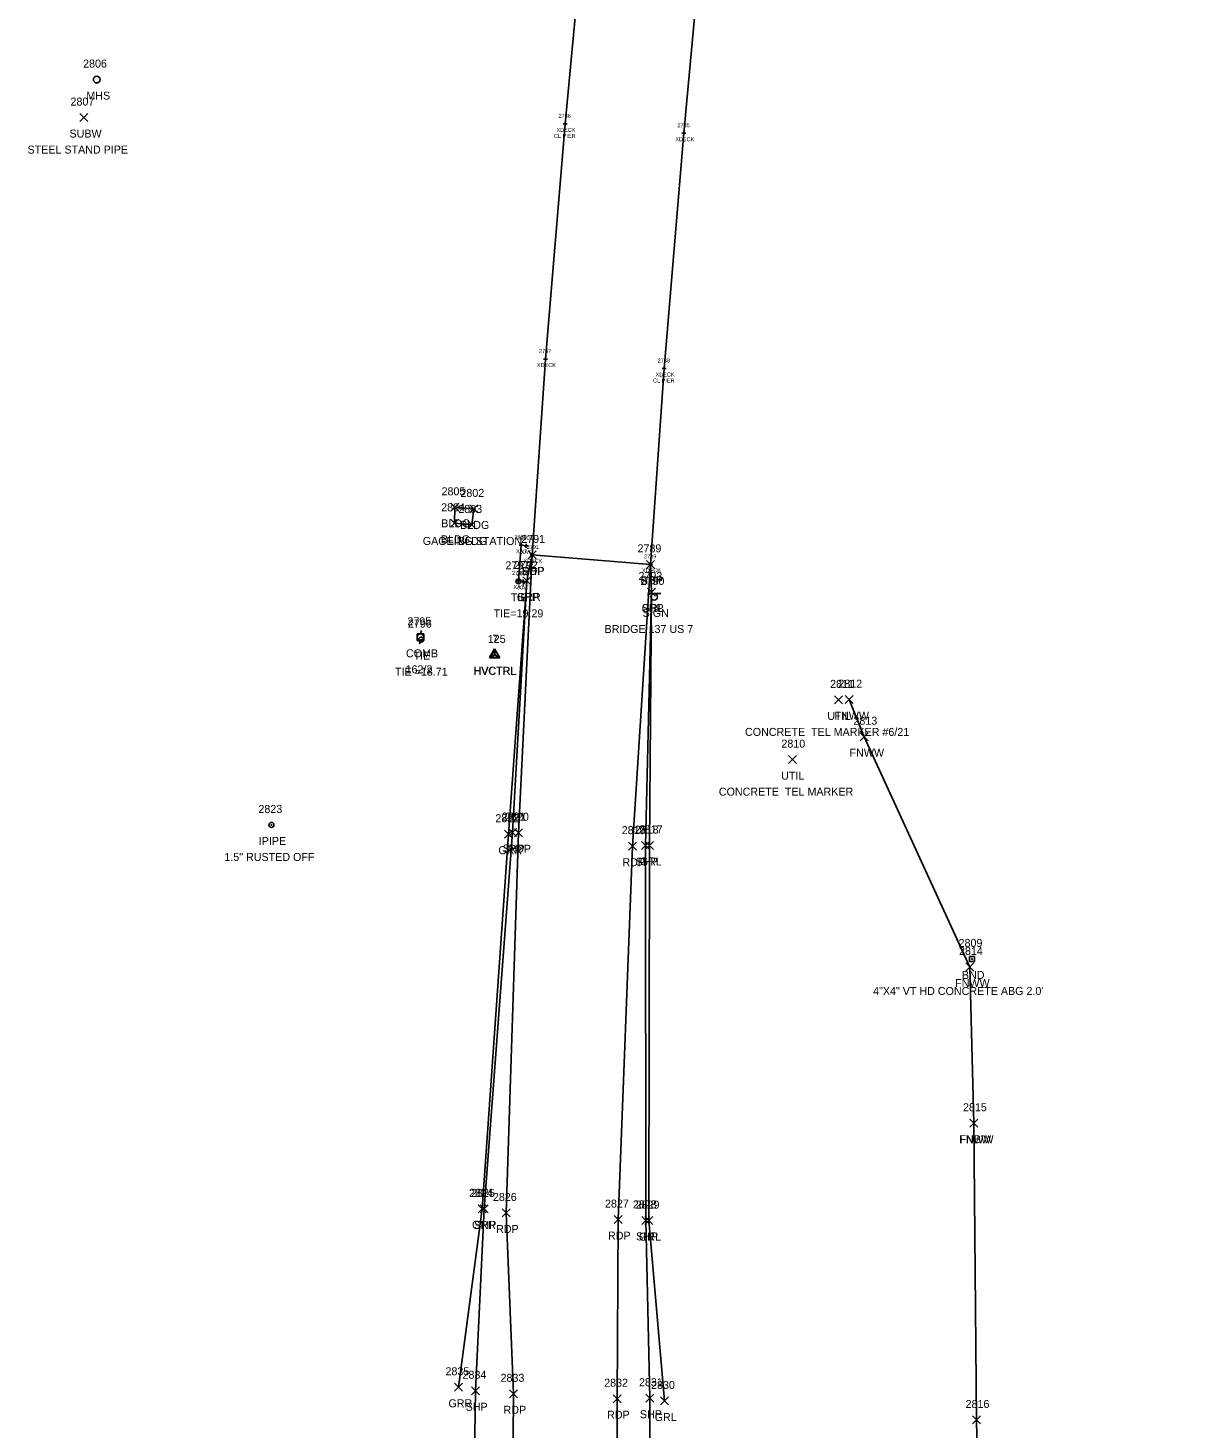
# Model space of a CAD drawing. Extents: x 1443071 to 1445292, y 614024 to 622563.
# Drawn here: x 1443904.7 to 1444198.2, y 619541.5 to 619891.2 of the extents above; entities that cross this region are included whole.
import ezdxf

# ---------------------------------------------------------------- set-up
doc = ezdxf.new("R2010")
doc.units = 0
for name, color, linetype in [('B_A', 7, 'Continuous'), ('B_C', 7, 'Continuous'), ('B_I', 7, 'Continuous'), ('B_TIC', 7, 'Continuous'), ('BELB', 7, 'Continuous'), ('BSUBM', 7, 'Continuous'), ('C_A', 7, 'Continuous'), ('C_C', 7, 'Continuous'), ('C_I', 7, 'Continuous'), ('CBP', 7, 'Continuous'), ('CPSM', 7, 'Continuous'), ('L_A', 7, 'Continuous'), ('L_C', 7, 'Continuous'), ('L_I', 7, 'Continuous'), ('L_TIC', 7, 'Continuous'), ('LBC', 7, 'Continuous'), ('LFNC', 7, 'Continuous'), ('M_A', 7, 'Continuous'), ('M_C', 7, 'Continuous'), ('M_I', 7, 'Continuous'), ('MHBP', 7, 'Continuous'), ('MPIP', 7, 'Continuous'), ('P_A', 7, 'Continuous'), ('P_I', 7, 'Continuous'), ('P_TIC', 7, 'Continuous'), ('PET', 7, 'Continuous'), ('PSP', 7, 'Continuous'), ('R_A', 7, 'Continuous'), ('R_I', 7, 'Continuous'), ('R_TIC', 7, 'Continuous'), ('RGR', 7, 'Continuous'), ('S_A', 7, 'Continuous'), ('S_C', 7, 'Continuous'), ('S_I', 7, 'Continuous'), ('SSGN', 7, 'Continuous'), ('U_A', 7, 'Continuous'), ('U_C', 7, 'Continuous'), ('U_I', 7, 'Continuous'), ('U_TIC', 7, 'Continuous'), ('UDEFAULT', 7, 'Continuous'), ('UP', 7, 'Continuous'), ('USMH', 7, 'Continuous')]:
    doc.layers.add(name, color=color, linetype=linetype)

msp = doc.modelspace()

# ---------------------------------------------------------------- linework, layer by layer
at = {"layer": 'B_TIC'}
for p, q in [((1444038.87, 619867.29), (1444038.95, 619867.29)), ((1444068.55, 619864.95), (1444068.62, 619864.95)), ((1444033.97, 619808.54), (1444034.05, 619808.54)), ((1444063.62, 619806.17), (1444063.69, 619806.17)), ((1444027.91, 619762.01), (1444027.98, 619762.01)), ((1444029.1, 619761.87), (1444029.18, 619761.87)), ((1444030.6, 619759.6), (1444030.67, 619759.6)), ((1444060.23, 619757.24), (1444060.31, 619757.24)), ((1444027.24, 619753.1), (1444027.32, 619753.1)), ((1444028.38, 619752.95), (1444028.45, 619752.95))]:
    msp.add_line(p, q, dxfattribs=at)
for points in [[(1444038.37, 619867.29), (1444039.37, 619867.29)], [(1444038.87, 619866.79), (1444038.87, 619867.79)], [(1444068.05, 619864.95), (1444069.05, 619864.95)], [(1444068.55, 619864.45), (1444068.55, 619865.45)], [(1444033.47, 619808.54), (1444034.47, 619808.54)], [(1444033.97, 619808.04), (1444033.97, 619809.04)], [(1444063.11, 619806.17), (1444064.11, 619806.17)], [(1444063.61, 619805.67), (1444063.61, 619806.67)], [(1444027.4, 619762.01), (1444028.4, 619762.01)], [(1444027.9, 619761.51), (1444027.9, 619762.51)], [(1444028.6, 619761.87), (1444029.6, 619761.87)], [(1444029.1, 619761.37), (1444029.1, 619762.37)], [(1444030.1, 619759.6), (1444031.1, 619759.6)], [(1444030.6, 619759.1), (1444030.6, 619760.1)], [(1444059.73, 619757.24), (1444060.73, 619757.24)], [(1444060.23, 619756.74), (1444060.23, 619757.74)], [(1444026.74, 619753.1), (1444027.74, 619753.1)], [(1444027.24, 619752.6), (1444027.24, 619753.6)], [(1444027.88, 619752.95), (1444028.88, 619752.95)], [(1444028.38, 619752.45), (1444028.38, 619753.45)]]:
    msp.add_lwpolyline(points, dxfattribs=at)
at = {"layer": 'BELB'}
for points in [[(1444043.42, 619916.17), (1444038.87, 619867.29), (1444033.97, 619808.54), (1444030.6, 619759.6)], [(1444073.05, 619913.75), (1444068.55, 619864.95), (1444063.61, 619806.17), (1444060.23, 619757.24)]]:
    msp.add_lwpolyline(points, dxfattribs=at)
at = {"layer": 'BSUBM'}
msp.add_lwpolyline([(1444028.38, 619752.95), (1444027.24, 619753.1), (1444027.9, 619762.01), (1444029.1, 619761.87)], dxfattribs=at)
at = {"layer": 'CBP'}
for centre, radius in [((1444027.22, 619753), 0.625), ((1444027.22, 619753), 0.0833), ((1444002.92, 619738.44), 0.625), ((1444002.92, 619738.44), 0.0833)]:
    msp.add_circle(centre, radius, dxfattribs=at)
at = {"layer": 'CPSM'}
for p, q in [((1444019.99, 619733.94), (1444021.24, 619736.1)), ((1444019.99, 619733.94), (1444021.24, 619734.66)), ((1444019.99, 619733.94), (1444022.49, 619733.94)), ((1444020.1, 619733.9), (1444021.35, 619736.07)), ((1444020.1, 619733.9), (1444021.35, 619734.62)), ((1444020.1, 619733.9), (1444022.6, 619733.9)), ((1444022.49, 619733.94), (1444021.24, 619736.1)), ((1444021.24, 619734.66), (1444021.24, 619736.1)), ((1444021.24, 619734.66), (1444021.24, 619734.66)), ((1444021.24, 619734.66), (1444022.49, 619733.94)), ((1444022.6, 619733.9), (1444021.35, 619736.07)), ((1444021.35, 619734.62), (1444021.35, 619736.07)), ((1444021.35, 619734.62), (1444021.35, 619734.62)), ((1444021.35, 619734.62), (1444022.6, 619733.9))]:
    msp.add_line(p, q, dxfattribs=at)
at = {"layer": 'L_TIC'}
for points in [[(1444010.34, 619770.49), (1444012.34, 619772.49)], [(1444012.34, 619770.49), (1444010.34, 619772.49)], [(1444010.34, 619770.49), (1444012.34, 619772.49)], [(1444012.34, 619770.49), (1444010.34, 619772.49)], [(1444015.05, 619770.09), (1444017.05, 619772.09)], [(1444017.05, 619770.09), (1444015.05, 619772.09)], [(1444015.05, 619770.09), (1444017.05, 619772.09)], [(1444017.05, 619770.09), (1444015.05, 619772.09)], [(1444010.23, 619766.5), (1444012.23, 619768.5)], [(1444012.23, 619766.5), (1444010.23, 619768.5)], [(1444014.53, 619766.09), (1444016.53, 619768.09)], [(1444016.53, 619766.09), (1444014.53, 619768.09)], [(1444108.81, 619722.44), (1444110.81, 619724.44)], [(1444110.81, 619722.44), (1444108.81, 619724.44)], [(1444112.59, 619713.18), (1444114.59, 619715.18)], [(1444114.59, 619713.18), (1444112.59, 619715.18)], [(1444138.95, 619655.65), (1444140.95, 619657.65)], [(1444140.95, 619655.65), (1444138.95, 619657.65)], [(1444139.95, 619616.62), (1444141.95, 619618.62)], [(1444141.95, 619616.62), (1444139.95, 619618.62)], [(1444139.95, 619616.62), (1444141.95, 619618.62)], [(1444141.95, 619616.62), (1444139.95, 619618.62)], [(1444140.66, 619542.48), (1444142.66, 619544.48)], [(1444142.66, 619542.48), (1444140.66, 619544.48)]]:
    msp.add_lwpolyline(points, dxfattribs=at)
at = {"layer": 'LBC'}
for points in [[(1444016.05, 619771.09), (1444015.53, 619767.09), (1444011.23, 619767.5), (1444011.34, 619771.49)], [(1444016.05, 619771.09), (1444011.34, 619771.49)]]:
    msp.add_lwpolyline(points, dxfattribs=at)
at = {"layer": 'LFNC'}
for points in [[(1444109.81, 619723.44), (1444113.59, 619714.18), (1444139.95, 619656.65), (1444140.95, 619617.62)], [(1444140.95, 619617.62), (1444141.66, 619543.48), (1444143.47, 619453.28), (1444144.69, 619378.28), (1444145.89, 619275.11), (1444147.59, 619182.81), (1444151.11, 619052.76), (1444160.95, 618964.58), (1444173.83, 618850.02), (1444185.25, 618752.69), (1444198.22, 618656.01)]]:
    msp.add_lwpolyline(points, dxfattribs=at)
at = {"layer": 'MHBP'}
msp.add_lwpolyline([(1444139.88, 619659.28), (1444141.13, 619659.28), (1444141.13, 619658.03), (1444139.88, 619658.03)], close=True, dxfattribs=at)
msp.add_circle((1444140.5, 619658.66), 0.0833, dxfattribs=at)
at = {"layer": 'MPIP'}
for radius in [0.625, 0.0833]:
    msp.add_circle((1443965.51, 619692.14), radius, dxfattribs=at)
at = {"layer": 'P_TIC'}
for points in [[(1444029.6, 619758.6), (1444031.6, 619760.6)], [(1444031.6, 619758.6), (1444029.6, 619760.6)], [(1444029.6, 619758.6), (1444031.6, 619760.6)], [(1444031.6, 619758.6), (1444029.6, 619760.6)], [(1444059.23, 619756.24), (1444061.23, 619758.24)], [(1444061.23, 619756.24), (1444059.23, 619758.24)], [(1444059.23, 619756.24), (1444061.23, 619758.24)], [(1444061.23, 619756.24), (1444059.23, 619758.24)], [(1444059.23, 619756.24), (1444061.23, 619758.24)], [(1444061.23, 619756.24), (1444059.23, 619758.24)], [(1444028.33, 619752.09), (1444030.33, 619754.09)], [(1444030.33, 619752.09), (1444028.33, 619754.09)], [(1444059.46, 619749.33), (1444061.46, 619751.33)], [(1444061.46, 619749.33), (1444059.46, 619751.33)], [(1444024.71, 619689.24), (1444026.71, 619691.24)], [(1444026.71, 619689.24), (1444024.71, 619691.24)], [(1444026.22, 619689.19), (1444028.22, 619691.19)], [(1444028.22, 619689.19), (1444026.22, 619691.19)], [(1444057.96, 619685.98), (1444059.96, 619687.98)], [(1444059.96, 619685.98), (1444057.96, 619687.98)], [(1444054.7, 619685.84), (1444056.7, 619687.84)], [(1444056.7, 619685.84), (1444054.7, 619687.84)], [(1444017.62, 619595.21), (1444019.62, 619597.21)], [(1444019.62, 619595.21), (1444017.62, 619597.21)], [(1444023.14, 619594.2), (1444025.14, 619596.2)], [(1444025.14, 619594.2), (1444023.14, 619596.2)], [(1444051.09, 619592.54), (1444053.09, 619594.54)], [(1444053.09, 619592.54), (1444051.09, 619594.54)], [(1444058.06, 619592.34), (1444060.06, 619594.34)], [(1444060.06, 619592.34), (1444058.06, 619594.34)], [(1444015.49, 619549.78), (1444017.49, 619551.78)], [(1444017.49, 619549.78), (1444015.49, 619551.78)], [(1444025, 619549.02), (1444027, 619551.02)], [(1444027, 619549.02), (1444025, 619551.02)], [(1444050.88, 619547.79), (1444052.88, 619549.79)], [(1444052.88, 619547.79), (1444050.88, 619549.79)], [(1444059.01, 619547.92), (1444061.01, 619549.92)], [(1444061.01, 619547.92), (1444059.01, 619549.92)]]:
    msp.add_lwpolyline(points, dxfattribs=at)
at = {"layer": 'PET'}
for points in [[(1444060.23, 619757.24), (1444030.6, 619759.6), (1444027.22, 619690.19), (1444024.14, 619595.2), (1444026, 619550.02), (1444025.36, 619470.06), (1444027.67, 619387.44), (1444035.05, 619262.29), (1444046.36, 619146.08), (1444057.76, 619040.09), (1444068.86, 618946.58), (1444081.65, 618839.75), (1444094.51, 618740.27), (1444109.49, 618620.85), (1444119.47, 618545.62)], [(1444060.23, 619757.24), (1444055.7, 619686.84), (1444052.09, 619593.54), (1444051.88, 619548.79), (1444051.53, 619469.84), (1444057.39, 619386.89), (1444060.43, 619264.84), (1444070.47, 619153.76), (1444082.27, 619042.98), (1444093.27, 618950.3), (1444106.23, 618841.72), (1444119.2, 618742.75), (1444134.15, 618623.05), (1444144.16, 618546.64)]]:
    msp.add_lwpolyline(points, dxfattribs=at)
at = {"layer": 'PSP'}
for points in [[(1444030.6, 619759.6), (1444029.33, 619753.09), (1444025.71, 619690.24), (1444018.62, 619596.21), (1444016.49, 619550.78), (1444015.83, 619506.94), (1444016.35, 619478.84), (1444019.52, 619385.97), (1444025.45, 619273.62), (1444031.18, 619208.3), (1444036.73, 619143.63), (1444046.33, 619051.58), (1444050.41, 619020.07), (1444060.07, 618945.31), (1444073.2, 618838.48), (1444085.76, 618739.52), (1444101.61, 618620.44), (1444111.35, 618544.8)], [(1444060.23, 619757.24), (1444060.46, 619750.33), (1444058.96, 619686.98), (1444059.06, 619593.34), (1444060.01, 619548.92), (1444060.2, 619469.56), (1444062.86, 619388.02), (1444070.04, 619265.9), (1444080.12, 619155.61), (1444092.23, 619044.26), (1444103.72, 618951.36), (1444117.15, 618842.88), (1444129.88, 618744.38), (1444144.78, 618624.26), (1444154.69, 618549.98)]]:
    msp.add_lwpolyline(points, dxfattribs=at)
at = {"layer": 'R_TIC'}
for points in [[(1444028.33, 619752.09), (1444030.33, 619754.09)], [(1444030.33, 619752.09), (1444028.33, 619754.09)], [(1444059.46, 619749.33), (1444061.46, 619751.33)], [(1444061.46, 619749.33), (1444059.46, 619751.33)], [(1444023.71, 619688.83), (1444025.71, 619690.83)], [(1444025.71, 619688.83), (1444023.71, 619690.83)], [(1444058.98, 619686.03), (1444060.98, 619688.03)], [(1444060.98, 619686.03), (1444058.98, 619688.03)], [(1444017.13, 619595.23), (1444019.13, 619597.23)], [(1444019.13, 619595.23), (1444017.13, 619597.23)], [(1444058.75, 619592.28), (1444060.75, 619594.28)], [(1444060.75, 619592.28), (1444058.75, 619594.28)], [(1444011.24, 619550.65), (1444013.24, 619552.65)], [(1444013.24, 619550.65), (1444011.24, 619552.65)], [(1444062.68, 619547.23), (1444064.68, 619549.23)], [(1444064.68, 619547.23), (1444062.68, 619549.23)]]:
    msp.add_lwpolyline(points, dxfattribs=at)
at = {"layer": 'RGR'}
for points in [[(1444029.33, 619753.09), (1444024.71, 619689.83), (1444018.13, 619596.23), (1444012.24, 619551.65)], [(1444060.46, 619750.33), (1444059.98, 619687.03), (1444059.75, 619593.28), (1444063.68, 619548.23)]]:
    msp.add_lwpolyline(points, dxfattribs=at)
at = {"layer": 'SSGN'}
for p, q in [((1444059.44, 619749.95), (1444062.78, 619749.95)), ((1444061.09, 619749.12), (1444061.09, 619749.12))]:
    msp.add_line(p, q, dxfattribs=at)
msp.add_circle((1444061.09, 619749.12), 0.833, dxfattribs=at)
at = {"layer": 'U_TIC'}
for points in [[(1443917.65, 619867.86), (1443919.65, 619869.86)], [(1443919.65, 619867.86), (1443917.65, 619869.86)]]:
    msp.add_lwpolyline(points, dxfattribs=at)
at = {"layer": 'UDEFAULT'}
for points in [[(1444106.2, 619722.38), (1444108.2, 619724.38)], [(1444108.2, 619722.38), (1444106.2, 619724.38)], [(1444094.68, 619707.45), (1444096.68, 619709.45)], [(1444096.68, 619707.45), (1444094.68, 619709.45)]]:
    msp.add_lwpolyline(points, dxfattribs=at)
at = {"layer": 'UP'}
for p, q in [((1444002.98, 619740.68), (1444002.73, 619739.85)), ((1444001.89, 619738.18), (1444001.89, 619739.85)), ((1444001.89, 619739.85), (1444003.56, 619739.85)), ((1444003.56, 619738.18), (1444001.89, 619738.18)), ((1444002.48, 619737.35), (1444002.73, 619738.18)), ((1444002.73, 619739.02), (1444002.73, 619739.02)), ((1444003.56, 619739.85), (1444003.56, 619738.18))]:
    msp.add_line(p, q, dxfattribs=at)
msp.add_circle((1444002.73, 619739.02), 0.833, dxfattribs=at)
at = {"layer": 'USMH'}
for p, q in [((1443921.85, 619878.35), (1443921.85, 619878.35)), ((1443922.69, 619878.35), (1443922.69, 619878.35))]:
    msp.add_line(p, q, dxfattribs=at)
msp.add_circle((1443921.85, 619878.35), 0.833, dxfattribs=at)

# ---------------------------------------------------------------- texts
at = {"layer": 'B_A'}
for s, p in [('XDECK', (1444036.71, 619865.29)), ('XDECK', (1444066.39, 619862.95)), ('XDECK', (1444031.81, 619806.54)), ('XDECK', (1444061.45, 619804.17)), ('XAT', (1444026.61, 619760.01)), ('XAT', (1444027.8, 619759.87)), ('XDECK', (1444028.44, 619757.6)), ('XDECK', (1444058.07, 619755.24)), ('XAT', (1444025.94, 619751.1)), ('XAT', (1444027.08, 619750.95))]:
    msp.add_text(s, height=1, dxfattribs=at).set_placement(p)
at = {"layer": 'B_C'}
for p in [(1444036.1, 619863.79), (1444060.84, 619802.67)]:
    msp.add_text('CL PIER', height=1, dxfattribs=at).set_placement(p)
at = {"layer": 'B_I'}
for s, p in [('2786', (1444037.21, 619868.79)), ('2785', (1444066.92, 619866.45)), ('2787', (1444032.34, 619810.04)), ('2788', (1444061.98, 619807.67)), ('2800', (1444026.19, 619763.51)), ('2801', (1444027.71, 619763.37)), ('2791', (1444029.25, 619761.1)), ('2789', (1444058.59, 619758.74)), ('2799', (1444025.6, 619754.6)), ('2798', (1444026.75, 619754.45))]:
    msp.add_text(s, height=1, dxfattribs=at).set_placement(p)
at = {"layer": 'C_A'}
for s, p in [('TIE', (1444025.3, 619748)), ('TIE', (1444001, 619733.44)), ('HVCTRL', (1444015.94, 619729.66)), ('HVCTRL', (1444016.04, 619729.62))]:
    msp.add_text(s, height=2, dxfattribs=at).set_placement(p)
at = {"layer": 'C_C'}
for s, p in [('TIE=19.29', (1444021.01, 619744)), ('TIE =18.71', (1443996.38, 619729.44))]:
    msp.add_text(s, height=2, dxfattribs=at).set_placement(p)
at = {"layer": 'C_I'}
for s, p in [('2797', (1444023.96, 619756)), ('2796', (1443999.6, 619741.44)), ('125', (1444019.55, 619737.62)), ('7', (1444020.68, 619737.66))]:
    msp.add_text(s, height=2, dxfattribs=at).set_placement(p)
at = {"layer": 'L_A'}
for s, p in [('BLDG', (1444007.93, 619766.49)), ('BLDG', (1444007.93, 619766.49)), ('BLDG', (1444012.64, 619766.09)), ('BLDG', (1444012.64, 619766.09)), ('BLDG', (1444007.83, 619762.5)), ('BLDG', (1444012.12, 619762.09)), ('FNWW', (1444106.16, 619718.44)), ('FNWW', (1444109.93, 619709.18)), ('FNWW', (1444136.3, 619651.65)), ('FNWW', (1444137.3, 619612.62)), ('FNBW', (1444137.42, 619612.62))]:
    msp.add_text(s, height=2, dxfattribs=at).set_placement(p)
at = {"layer": 'L_C'}
msp.add_text('GAGEING STATION', height=2, dxfattribs=at).set_placement((1444003.31, 619762.09))
msp.add_text('GAGEING STATION', height=2, dxfattribs=at).set_placement((1444003.31, 619762.09))
at = {"layer": 'L_I'}
for s, p in [('2805', (1444008, 619774.49)), ('2805', (1444008, 619774.49)), ('2802', (1444012.71, 619774.09)), ('2802', (1444012.71, 619774.09)), ('2804', (1444007.9, 619770.5)), ('2803', (1444012.19, 619770.09)), ('2812', (1444107.12, 619726.44)), ('2813', (1444110.89, 619717.18)), ('2814', (1444137.26, 619659.65)), ('2815', (1444138.26, 619620.62)), ('2815', (1444138.26, 619620.62)), ('2816', (1444138.91, 619546.48))]:
    msp.add_text(s, height=2, dxfattribs=at).set_placement(p)
at = {"layer": 'M_A'}
for s, p in [('IPIPE', (1443962.34, 619687.14)), ('BND', (1444137.99, 619653.66))]:
    msp.add_text(s, height=2, dxfattribs=at).set_placement(p)
at = {"layer": 'M_C'}
for s, p in [('1.5" RUSTED OFF', (1443953.75, 619683.14)), ('4"X4" VT HD CONCRETE ABG 2.0\'', (1444115.81, 619649.66))]:
    msp.add_text(s, height=2, dxfattribs=at).set_placement(p)
at = {"layer": 'M_I'}
for s, p in [('2823', (1443962.25, 619695.14)), ('2809', (1444137.16, 619661.66))]:
    msp.add_text(s, height=2, dxfattribs=at).set_placement(p)
at = {"layer": 'P_A'}
for s, p in [('SHP', (1444028.13, 619754.6)), ('RDP', (1444028.08, 619754.6)), ('SHP', (1444057.76, 619752.24)), ('RDP', (1444057.71, 619752.24)), ('RDP', (1444057.71, 619752.24)), ('SHP', (1444026.86, 619748.09)), ('SHP', (1444057.99, 619745.33)), ('SHP', (1444023.25, 619685.24)), ('RDP', (1444024.71, 619685.19)), ('RDP', (1444053.19, 619681.84)), ('SHP', (1444056.49, 619681.98)), ('SHP', (1444016.16, 619591.21)), ('RDP', (1444021.63, 619590.2)), ('RDP', (1444049.58, 619588.54)), ('SHP', (1444056.59, 619588.34)), ('SHP', (1444014.02, 619545.78)), ('RDP', (1444023.49, 619545.02)), ('RDP', (1444049.36, 619543.79)), ('SHP', (1444057.54, 619543.92))]:
    msp.add_text(s, height=2, dxfattribs=at).set_placement(p)
at = {"layer": 'P_I'}
for s, p in [('2791', (1444027.9, 619762.6)), ('2791', (1444027.9, 619762.6)), ('2789', (1444056.96, 619760.24)), ('2789', (1444056.96, 619760.24)), ('2789', (1444056.96, 619760.24)), ('2792', (1444026.07, 619756.09)), ('2793', (1444057.2, 619753.33)), ('2821', (1444023.02, 619693.24)), ('2820', (1444023.87, 619693.19)), ('2819', (1444053, 619689.84)), ('2818', (1444056.26, 619689.98)), ('2825', (1444015.36, 619599.21)), ('2826', (1444020.83, 619598.2)), ('2827', (1444048.83, 619596.54)), ('2828', (1444055.8, 619596.34)), ('2834', (1444013.23, 619553.78)), ('2833', (1444022.74, 619553.02)), ('2832', (1444048.62, 619551.79)), ('2831', (1444057.32, 619551.92))]:
    msp.add_text(s, height=2, dxfattribs=at).set_placement(p)
at = {"layer": 'R_A'}
for s, p in [('GRR', (1444026.82, 619748.09)), ('GRL', (1444058, 619745.33)), ('GRR', (1444022.19, 619684.83)), ('GRL', (1444057.53, 619682.03)), ('GRR', (1444015.62, 619591.23)), ('GRL', (1444057.3, 619588.28)), ('GRR', (1444009.73, 619546.65)), ('GRL', (1444061.23, 619543.23))]:
    msp.add_text(s, height=2, dxfattribs=at).set_placement(p)
at = {"layer": 'R_I'}
for s, p in [('2792', (1444026.07, 619756.09)), ('2793', (1444057.2, 619753.33)), ('2822', (1444021.45, 619692.83)), ('2817', (1444057.29, 619690.03)), ('2824', (1444014.87, 619599.23)), ('2829', (1444056.48, 619596.28)), ('2835', (1444008.98, 619554.65)), ('2830', (1444060.34, 619551.23))]:
    msp.add_text(s, height=2, dxfattribs=at).set_placement(p)
at = {"layer": 'S_A'}
msp.add_text('SIGN', height=2, dxfattribs=at).set_placement((1444058.23, 619744.1))
at = {"layer": 'S_C'}
msp.add_text('BRIDGE 137 US 7', height=2, dxfattribs=at).set_placement((1444048.72, 619740.1))
at = {"layer": 'S_I'}
msp.add_text('2790', height=2, dxfattribs=at).set_placement((1444057.72, 619752.1))
at = {"layer": 'U_A'}
for s, p in [('MHS', (1443919.27, 619873.35)), ('SUBW', (1443915.06, 619863.86)), ('COMB', (1443999.11, 619734.02)), ('UTIL', (1444104.37, 619718.38)), ('UTIL', (1444092.84, 619703.45))]:
    msp.add_text(s, height=2, dxfattribs=at).set_placement(p)
at = {"layer": 'U_C'}
for s, p in [('STEEL STAND PIPE', (1443904.57, 619859.86)), ('162/2', (1443999.01, 619730.02)), ('CONCRETE  TEL MARKER #6/21', (1444083.81, 619714.38)), ('CONCRETE  TEL MARKER', (1444077.27, 619699.45))]:
    msp.add_text(s, height=2, dxfattribs=at).set_placement(p)
at = {"layer": 'U_I'}
for s, p in [('2806', (1443918.46, 619881.35)), ('2807', (1443915.31, 619871.86)), ('2795', (1443999.47, 619742.02)), ('2811', (1444105.07, 619726.38)), ('2810', (1444092.9, 619711.45))]:
    msp.add_text(s, height=2, dxfattribs=at).set_placement(p)

doc.saveas('drawing.dxf')
